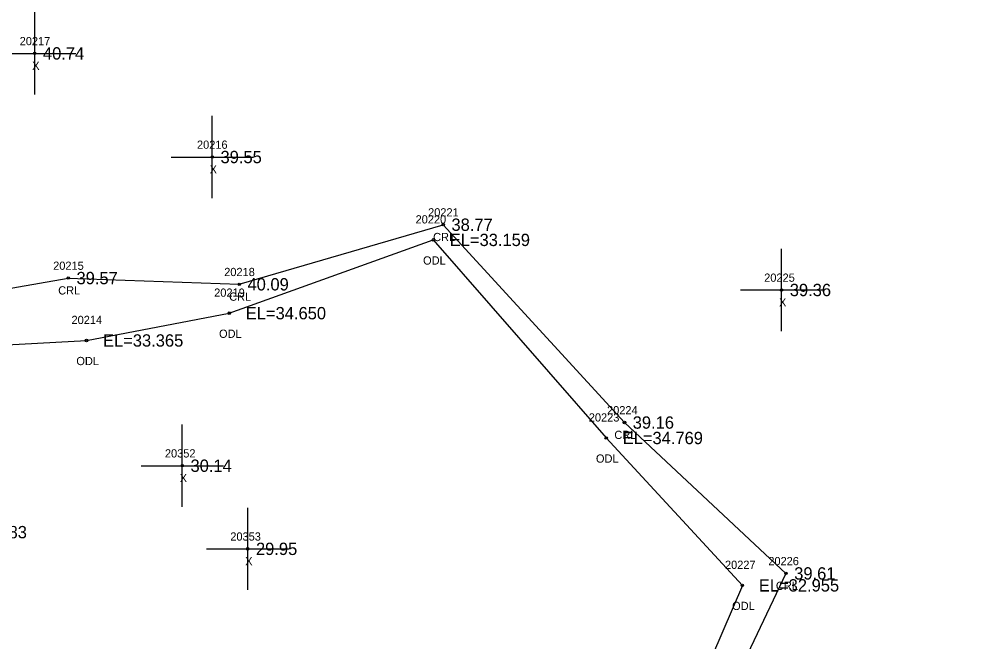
# Model space of a CAD drawing. Extents: x 2619569 to 2620117, y 784503 to 785150.
# Drawn here: x 2619897.7 to 2620013.8, y 784823.9 to 784899.6 of the extents above; entities that cross this region are included whole.
import ezdxf

# ---------------------------------------------------------------- set-up
doc = ezdxf.new("R2010")
doc.units = 0
for name, color, linetype in [('RD_EX_H2O', 7, 'Continuous'), ('RD_EX_H2O_txCode', 7, 'Continuous'), ('RD_EX_Misc', 7, 'Continuous'), ('RD_EX_Misc_txCode', 7, 'Continuous'), ('RD_EX_TX_H2O_ELEV', 7, 'Continuous'), ('RD_EX_TX_Misc_ELEV', 7, 'Continuous'), ('RD_SMD_Locator', 7, 'Continuous')]:
    doc.layers.add(name, color=color, linetype=linetype)

msp = doc.modelspace()

# ---------------------------------------------------------------- linework, layer by layer
at = {"layer": 'RD_EX_H2O'}
for points in [[(2619850.74, 784850.04), (2619858.56, 784858.85), (2619863.71, 784859.84), (2619875.95, 784863.3), (2619903.67, 784868.12), (2619924.46, 784867.36), (2619949.26, 784874.61), (2619971.3, 784850.55), (2619990.94, 784832.2), (2619978.09, 784805.14), (2619980.54, 784803.04), (2620013.79, 784776.16)], [(2619849.21, 784838.05), (2619855.06, 784843.73), (2619862.98, 784854.68), (2619876.77, 784858.94), (2619905.89, 784860.53), (2619923.25, 784863.85), (2619948.05, 784872.76), (2619969.08, 784848.67), (2619985.64, 784830.75), (2619975.85, 784807.96), (2619978.05, 784802.93), (2620013.48, 784773.68)]]:
    msp.add_lwpolyline(points, dxfattribs=at)
at = {"layer": 'RD_EX_Misc'}
for p, q in [((2619899.59, 784890.44), (2619899.59, 784900.44)), ((2619894.59, 784895.44), (2619904.59, 784895.44)), ((2619921.18, 784877.84), (2619921.18, 784887.84)), ((2619916.18, 784882.84), (2619926.18, 784882.84)), ((2619990.4, 784861.67), (2619990.4, 784871.67)), ((2619985.4, 784866.67), (2619995.4, 784866.67)), ((2619917.53, 784840.3), (2619917.53, 784850.3)), ((2619912.53, 784845.3), (2619922.53, 784845.3)), ((2619925.49, 784830.19), (2619925.49, 784840.19)), ((2619920.49, 784835.19), (2619930.49, 784835.19))]:
    msp.add_line(p, q, dxfattribs=at)
at = {"layer": 'RD_SMD_Locator'}
for centre in [(2619899.59, 784895.44), (2619921.18, 784882.84), (2619949.26, 784874.61), (2619948.05, 784872.76), (2619903.67, 784868.12), (2619924.46, 784867.36), (2619990.4, 784866.67), (2619923.25, 784863.85), (2619905.89, 784860.53), (2619971.3, 784850.55), (2619969.08, 784848.67), (2619917.53, 784845.3), (2619925.49, 784835.19), (2619990.94, 784832.2), (2619985.64, 784830.75)]:
    msp.add_circle(centre, 0.15, dxfattribs=at)

# ---------------------------------------------------------------- texts
at = {"layer": 'RD_EX_H2O_txCode'}
for s, p in [('20221', (2619947.42, 784875.61)), ('20220', (2619945.9, 784874.76)), ('CRL', (2619948.03, 784872.61)), ('20215', (2619901.83, 784869.12)), ('ODL', (2619946.81, 784869.76)), ('20218', (2619922.63, 784868.36)), ('CRL', (2619902.44, 784866.12)), ('20219', (2619921.41, 784865.85)), ('CRL', (2619923.23, 784865.36)), ('20214', (2619904.06, 784862.53)), ('ODL', (2619922, 784860.85)), ('ODL', (2619904.65, 784857.53)), ('20224', (2619969.18, 784851.55)), ('20223', (2619966.96, 784850.67)), ('CRL', (2619970.07, 784848.55)), ('ODL', (2619967.83, 784845.67)), ('20227', (2619983.52, 784832.75)), ('20226', (2619988.79, 784833.2)), ('CRL', (2619989.71, 784830.2)), ('ODL', (2619984.39, 784827.75))]:
    msp.add_text(s, height=1, dxfattribs=at).set_placement(p)
at = {"layer": 'RD_EX_Misc_txCode'}
for s, p in [('20217', (2619897.76, 784896.44)), ('X', (2619899.28, 784893.44)), ('20216', (2619919.32, 784883.84)), ('X', (2619920.86, 784880.84)), ('20225', (2619988.29, 784867.67)), ('X', (2619990.09, 784864.67)), ('20352', (2619915.42, 784846.3)), ('X', (2619917.22, 784843.3)), ('20353', (2619923.37, 784836.19)), ('X', (2619925.18, 784833.19))]:
    msp.add_text(s, height=1, dxfattribs=at).set_placement(p)
at = {"layer": 'RD_EX_TX_H2O_ELEV'}
for s, p in [('38.77', (2619950.26, 784873.86)), ('EL=33.159', (2619950.05, 784872.01)), ('39.57', (2619904.67, 784867.37)), ('40.09', (2619925.46, 784866.61)), ('EL=34.650', (2619925.25, 784863.1)), ('EL=33.365', (2619907.89, 784859.78)), ('39.16', (2619972.3, 784849.8)), ('EL=34.769', (2619971.08, 784847.92)), ('39.61', (2619991.94, 784831.45)), ('EL=32.955', (2619987.64, 784830))]:
    msp.add_text(s, height=1.5, dxfattribs=at).set_placement(p)
at = {"layer": 'RD_EX_TX_Misc_ELEV'}
for s, p in [('40.74', (2619900.59, 784894.69)), ('39.55', (2619922.18, 784882.09)), ('39.36', (2619991.4, 784865.92)), ('30.14', (2619918.53, 784844.55)), ('28.83', (2619893.62, 784836.47)), ('29.95', (2619926.49, 784834.44))]:
    msp.add_text(s, height=1.5, dxfattribs=at).set_placement(p)

doc.saveas('drawing.dxf')
